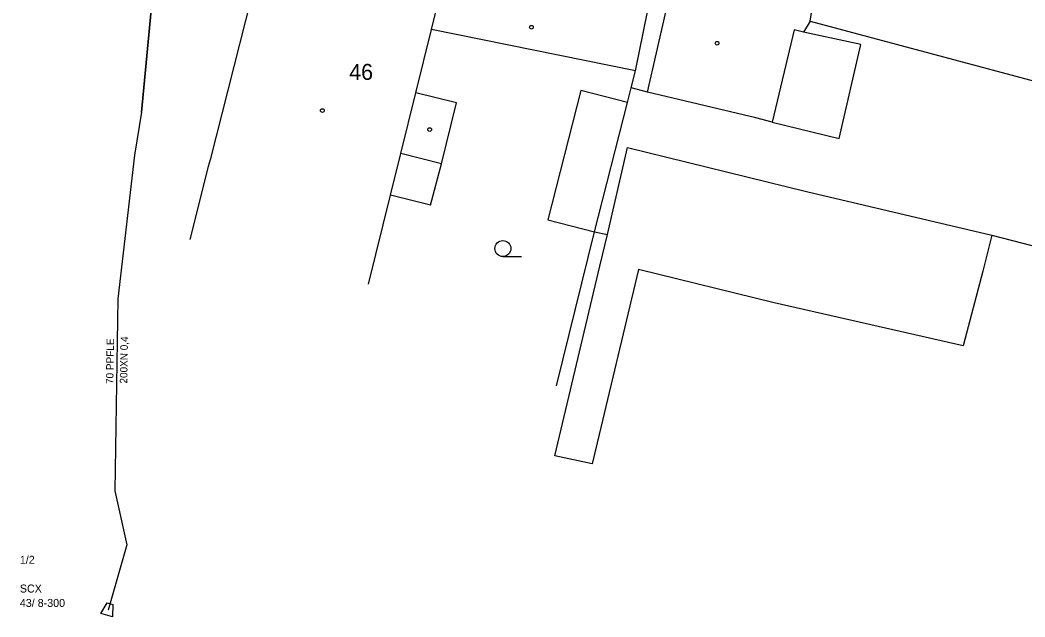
# Model space of a CAD drawing. Extents: x -836739 to -834468, y -1071001 to -1070126.
# Drawn here: x -836651.43 to -836604.33, y -1070483.07 to -1070455.07 of the extents above; entities that cross this region are included whole.
import ezdxf

# ---------------------------------------------------------------- set-up
doc = ezdxf.new("R2010")
doc.units = 0
for name, color, linetype in [('f001_pol_linie', 7, 'Continuous'), ('f001_pol_texty', 7, 'Continuous'), ('f001_pol_znacky', 7, 'Continuous'), ('f006_osa_trasy', 7, 'Continuous'), ('f307_kabel_metal', 7, 'Continuous'), ('f307_kabel_metal_ann', 7, 'Continuous'), ('f307_spojka_metal', 7, 'Continuous'), ('f307_spojka_metal_ann', 7, 'Continuous')]:
    doc.layers.add(name, color=color, linetype=linetype)

msp = doc.modelspace()

# ---------------------------------------------------------------- linework, layer by layer
at = {"layer": 'f001_pol_linie'}
for points in [[(-836614.4, -1070455.13), (-836613.73, -1070450.82), (-836612.88, -1070445.29), (-836612.82, -1070444.93)], [(-836616.17, -1070459.86), (-836616.95, -1070459.66), (-836622.02, -1070458.45), (-836620.76, -1070452.9), (-836617.02, -1070453.79), (-836616.09, -1070450.28), (-836613.73, -1070450.82)], [(-836639.76, -1070450.7), (-836642.52, -1070461.63), (-836642.61, -1070461.95), (-836643.47, -1070465.37)], [(-836635.09, -1070467.46), (-836634.06, -1070463.28), (-836633.58, -1070461.34), (-836632.88, -1070458.48), (-836632.14, -1070455.52), (-836631.47, -1070452.78)], [(-836622.58, -1070457.45), (-836622.02, -1070454.69)], [(-836622.58, -1070457.45), (-836632.14, -1070455.52)], [(-836614.4, -1070455.13), (-836614.71, -1070455.64), (-836615.15, -1070455.54), (-836616.17, -1070459.86)], [(-836614.4, -1070455.13), (-836593.77, -1070460.64)], [(-836616.17, -1070459.86), (-836613.04, -1070460.63), (-836612.02, -1070456.22), (-836614.71, -1070455.64)], [(-836622.96, -1070458.94), (-836622.78, -1070458.25), (-836622.58, -1070457.45)], [(-836626.69, -1070464.45), (-836624.5, -1070465.01), (-836622.96, -1070458.94), (-836625.15, -1070458.38), (-836626.69, -1070464.45)], [(-836622.02, -1070458.45), (-836622.78, -1070458.25)], [(-836630.97, -1070458.95), (-836632.88, -1070458.48)], [(-836631.68, -1070461.82), (-836630.97, -1070458.95)], [(-836626.37, -1070475.52), (-836624.25, -1070466.62), (-836623.9, -1070465.13), (-836622.96, -1070461.05), (-836614.56, -1070463.12), (-836605.88, -1070465.16), (-836606.31, -1070466.85), (-836607.22, -1070470.35), (-836616.08, -1070468.33), (-836622.44, -1070466.77), (-836624.62, -1070475.89), (-836626.37, -1070475.52)], [(-836631.68, -1070461.82), (-836633.58, -1070461.34)], [(-836632.19, -1070463.75), (-836631.68, -1070461.82)], [(-836632.19, -1070463.75), (-836634.06, -1070463.28)], [(-836626.28, -1070472.23), (-836624.5, -1070465.01)], [(-836624.5, -1070465.01), (-836623.9, -1070465.13)], [(-836605.88, -1070465.16), (-836594.82, -1070468.03), (-836588.62, -1070469.44)]]:
    msp.add_lwpolyline(points, dxfattribs=at)
at = {"layer": 'f001_pol_znacky'}
msp.add_line((-836628.8, -1070466.165), (-836627.925, -1070466.165), dxfattribs=at)
for centre, radius in [((-836627.46, -1070455.41), 0.0875), ((-836618.76, -1070456.16), 0.0875), ((-836637.26, -1070459.32), 0.0875), ((-836632.23, -1070460.21), 0.0875), ((-836628.8, -1070465.79), 0.375)]:
    msp.add_circle(centre, radius, dxfattribs=at)
at = {"layer": 'f006_osa_trasy'}
msp.add_lwpolyline([(-836645.74, -1070459.39), (-836645.14, -1070453.11), (-836643.43, -1070446.36), (-836641.92, -1070441.74), (-836641.329, -1070439.75)], dxfattribs=at)
at = {"layer": 'f307_kabel_metal'}
msp.add_lwpolyline([(-836634.1, -1070416.7), (-836634.565, -1070418.121), (-836635.014, -1070419.495), (-836636.012, -1070422.545), (-836636.235, -1070423.267), (-836638.25, -1070429.76), (-836640.07, -1070435.51), (-836642.018, -1070442.071), (-836643.43, -1070446.36), (-836645.14, -1070453.11), (-836645.74, -1070459.39), (-836646.07, -1070461.41), (-836646.84, -1070468.15), (-836646.99, -1070477.15), (-836646.42, -1070479.69), (-836647.3, -1070482.75)], dxfattribs=at)
at = {"layer": 'f307_spojka_metal'}
msp.add_lwpolyline([(-836647.078, -1070482.489), (-836647.099, -1070483.068), (-836647.639, -1070482.913), (-836647.349, -1070482.411)], close=True, dxfattribs=at)

# ---------------------------------------------------------------- texts
at = {"layer": 'f001_pol_texty'}
msp.add_text('46', height=0.75, dxfattribs=at).set_placement((-836636, -1070457.88))
at = {"layer": 'f307_kabel_metal_ann'}
for s, p in [('70 PPFLE', (-836647.057, -1070472.145)), (' 200XN 0,4', (-836646.408, -1070472.255))]:
    msp.add_text(s, height=0.35, rotation=89.05, dxfattribs=at).set_placement(p)
at = {"layer": 'f307_spojka_metal_ann'}
for s, p in [('1/2', (-836651.439, -1070480.575)), ('SCX', (-836651.439, -1070481.925)), ('43/ 8-300', (-836651.439, -1070482.6))]:
    msp.add_text(s, height=0.375, dxfattribs=at).set_placement(p)

doc.saveas('drawing.dxf')
